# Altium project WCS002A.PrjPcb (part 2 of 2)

## Sheet WCS002A_HostInterface_ADC.SchDoc: Host Interface
size 558 x 431 mm; Date: Not shown in title block; ApprovedBy: Not shown in title block; CheckedBy: Not shown in title block; Author: Not shown in title block; CompanyName: Not shown in title block; Engineer: Not shown in title block; Organization: Not shown in title block; Address1: Not shown in title block; Address2: Not shown in title block; Address3: Not shown in title block; Address4: Not shown in title block; DocumentNumber: 3; Revision: Use project parameter SCH_Rev; SheetNumber: 3; SheetTotal: 6; PageSetup: Record=PageOptions¦CenterHorizontal=True¦CenterVertical=True¦PrintScale=1.00¦XCorrection=1.00¦YCorrection=1.00¦PrintKind=0¦BorderSize=5000000¦LeftOffset=0¦BottomOffset=0¦Orientation=2¦PaperLength=1000¦PaperWidth=1000¦Scale=100¦PaperSource=15¦PrintQuality=600¦MediaType=1¦DitherType=10¦PaperKind=Letter¦PrintScaleMode=1
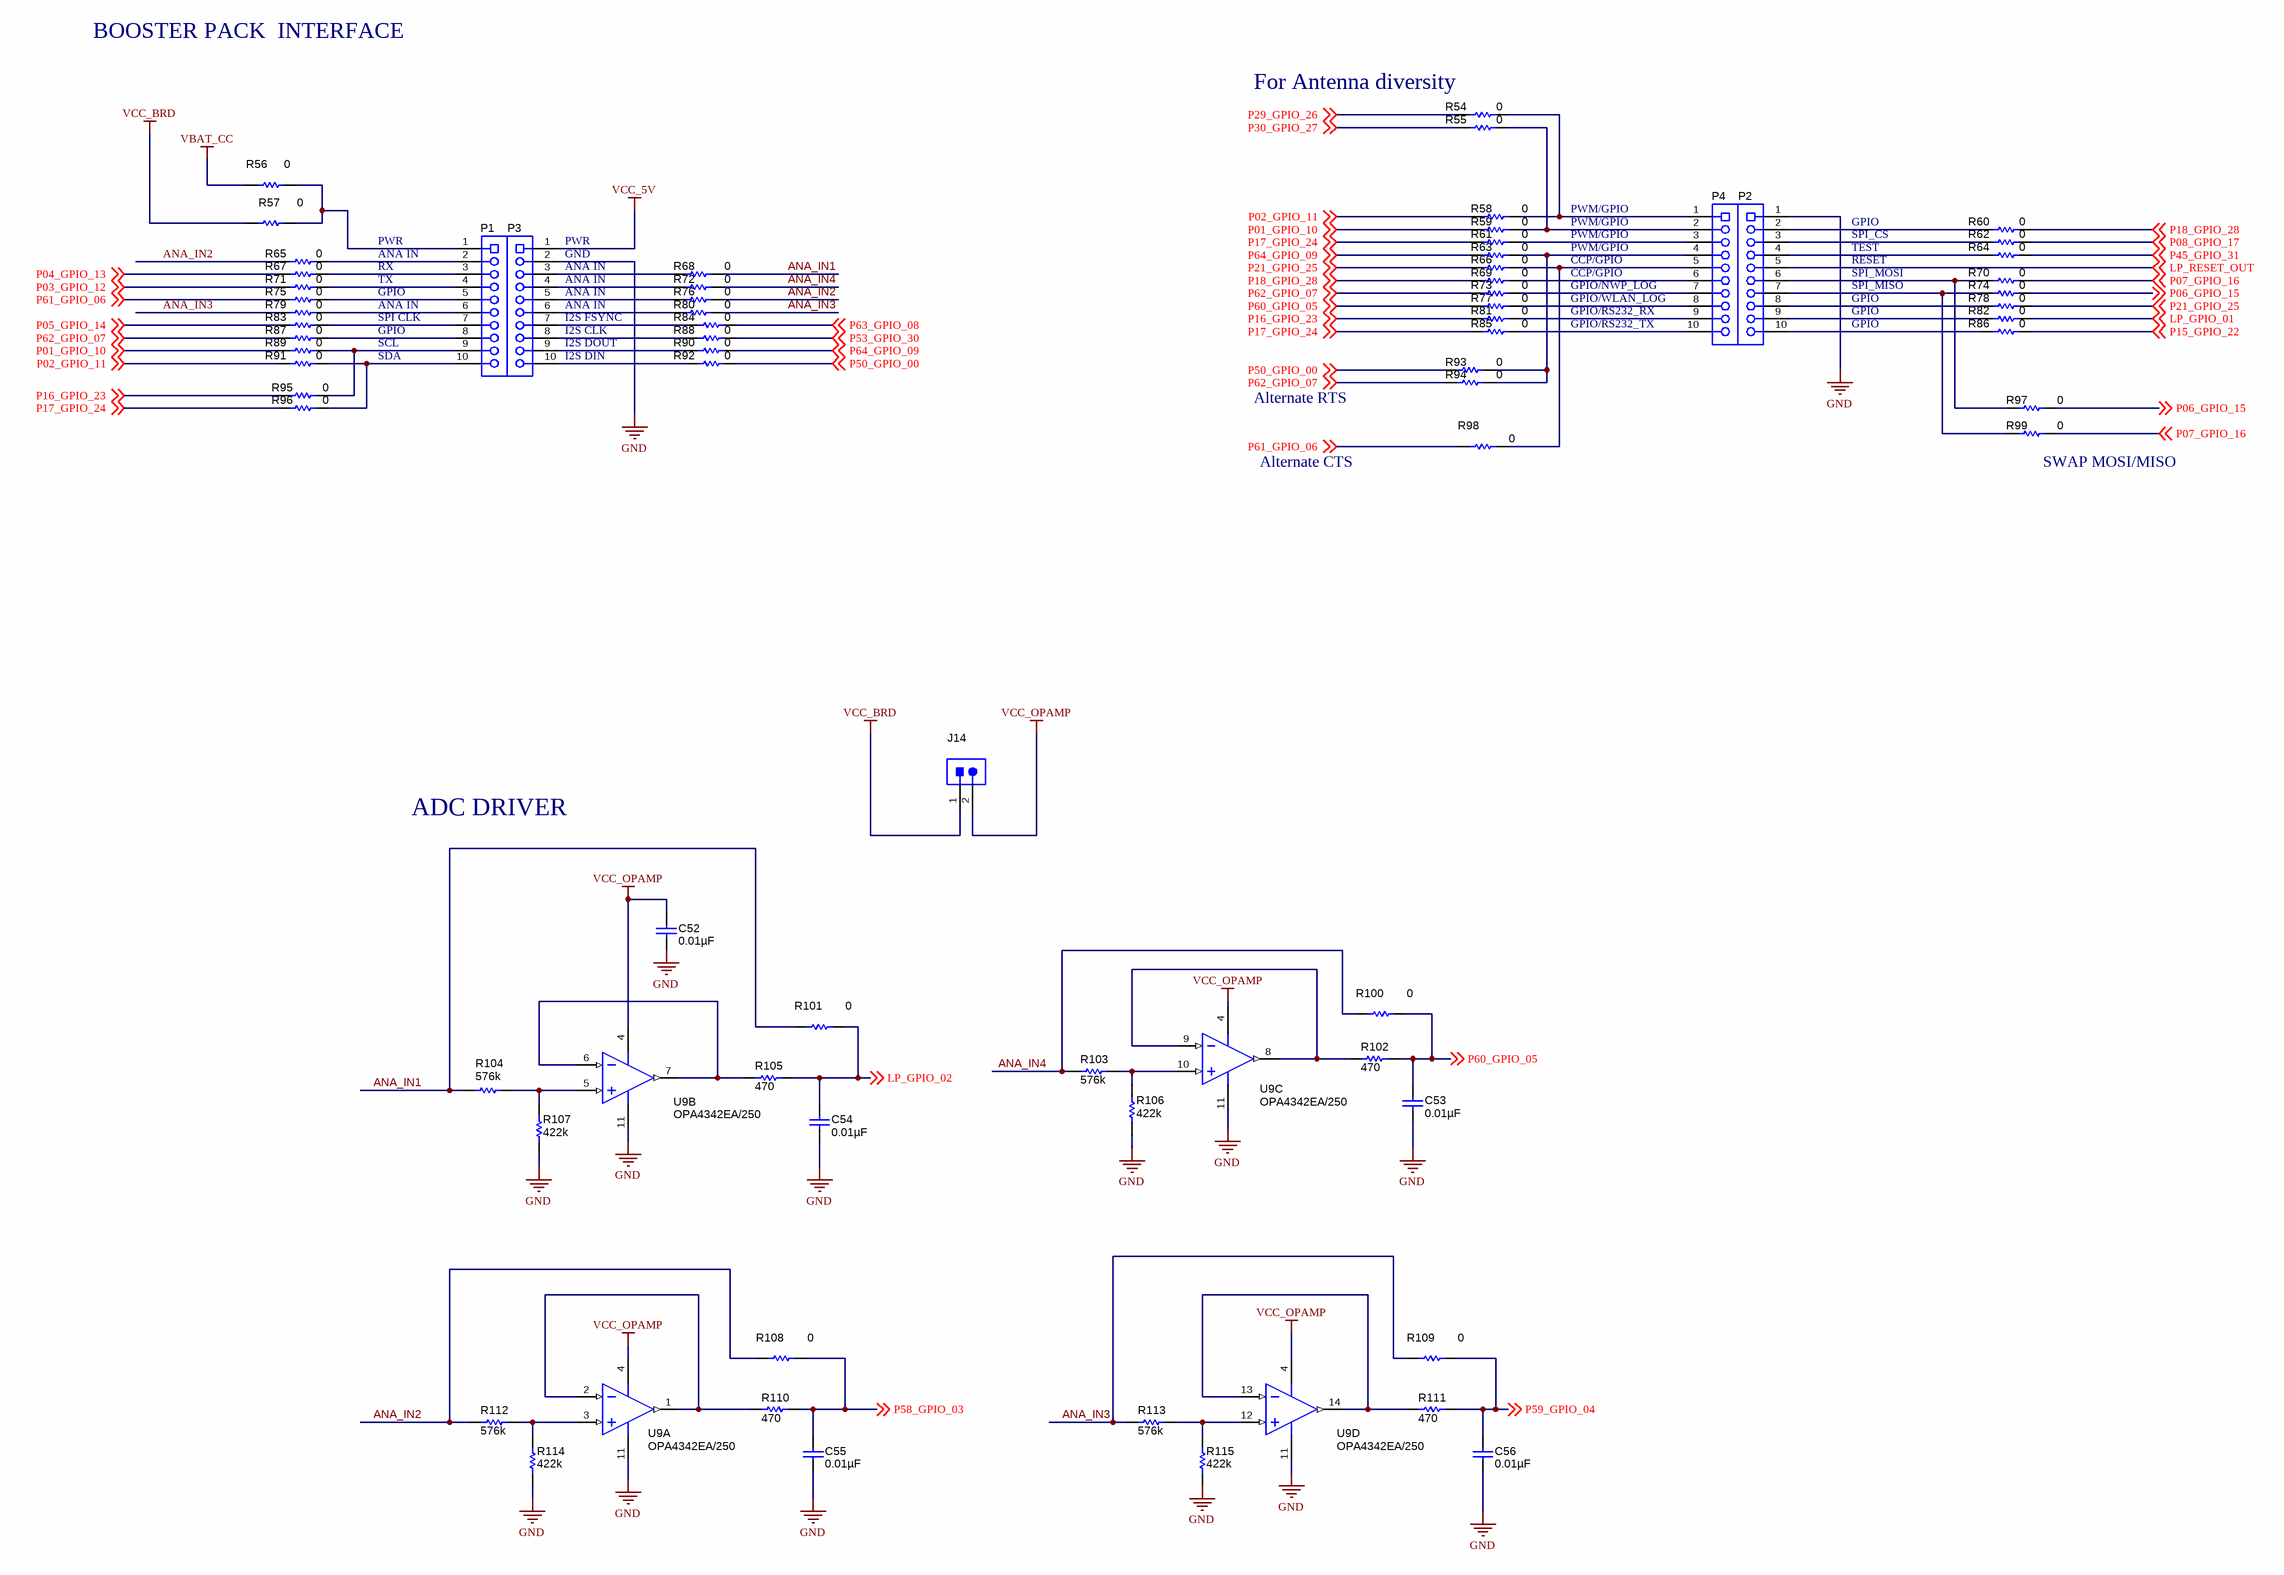
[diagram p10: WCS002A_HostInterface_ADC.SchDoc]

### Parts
C52  ValueDisplayed: 0.01µF  [0402]  (hidden comment: GRM155R61A103KA01D)
C53  ValueDisplayed: 0.01µF  [0402]  (hidden comment: C1005X7R1C103K)
C54  ValueDisplayed: 0.01µF  [0402]  (hidden comment: C1005X7R1C103K)
C55  ValueDisplayed: 0.01µF  [0402]  (hidden comment: C1005X7R1C103K)
C56  ValueDisplayed: 0.01µF  [0402]  (hidden comment: C1005X7R1C103K)
J14  61300211121  [WURTH_61300211121]  (value not drawn)
P1  SSW-110-23-F-S  [CONN_SSW-110-23-F-S]  (value not drawn)
P2  SSW-110-23-F-S  [CONN_SSW-110-23-F-S]  (value not drawn)
P3  SSW-110-23-F-S  [CONN_SSW-110-23-F-S]  (value not drawn)
P4  SSW-110-23-F-S  [CONN_SSW-110-23-F-S]  (value not drawn)
R54  ValueDisplayed: 0  [0402]  (hidden comment: ERJ-2GE0R00X)
R55  ValueDisplayed: 0  [0402]  (hidden comment: ERJ-2GE0R00X)
R56  ValueDisplayed: 0  [0603]  (hidden comment: ERJ-3GEY0R00V)
R57  ValueDisplayed: 0  [0603]  (hidden comment: ERJ-3GEY0R00V)
R58  ValueDisplayed: 0  [0402]  (hidden comment: ERJ-2GE0R00X)
R59  ValueDisplayed: 0  [0402]  (hidden comment: ERJ-2GE0R00X)
R60  ValueDisplayed: 0  [0402]  (hidden comment: ERJ-2GE0R00X)
R61  ValueDisplayed: 0  [0402]  (hidden comment: ERJ-2GE0R00X)
R62  ValueDisplayed: 0  [0402]  (hidden comment: ERJ-2GE0R00X)
R63  ValueDisplayed: 0  [0402]  (hidden comment: ERJ-2GE0R00X)
R64  ValueDisplayed: 0  [0402]  (hidden comment: ERJ-2GE0R00X)
R65  ValueDisplayed: 0  [0402]  (hidden comment: ERJ-2GE0R00X)
R66  ValueDisplayed: 0  [0402]  (hidden comment: ERJ-2GE0R00X)
R67  ValueDisplayed: 0  [0402]  (hidden comment: ERJ-2GE0R00X)
R68  ValueDisplayed: 0  [0402]  (hidden comment: ERJ-2GE0R00X)
R69  ValueDisplayed: 0  [0402]  (hidden comment: ERJ-2GE0R00X)
R70  ValueDisplayed: 0  [0402]  (hidden comment: ERJ-2GE0R00X)
R71  ValueDisplayed: 0  [0402]  (hidden comment: ERJ-2GE0R00X)
R72  ValueDisplayed: 0  [0402]  (hidden comment: ERJ-2GE0R00X)
R73  ValueDisplayed: 0  [0402]  (hidden comment: ERJ-2GE0R00X)
R74  ValueDisplayed: 0  [0402]  (hidden comment: ERJ-2GE0R00X)
R75  ValueDisplayed: 0  [0402]  (hidden comment: ERJ-2GE0R00X)
R76  ValueDisplayed: 0  [0402]  (hidden comment: ERJ-2GE0R00X)
R77  ValueDisplayed: 0  [0402]  (hidden comment: ERJ-2GE0R00X)
R78  ValueDisplayed: 0  [0402]  (hidden comment: ERJ-2GE0R00X)
R79  ValueDisplayed: 0  [0402]  (hidden comment: ERJ-2GE0R00X)
R80  ValueDisplayed: 0  [0402]  (hidden comment: ERJ-2GE0R00X)
R81  ValueDisplayed: 0  [0402]  (hidden comment: ERJ-2GE0R00X)
R82  ValueDisplayed: 0  [0402]  (hidden comment: ERJ-2GE0R00X)
R83  ValueDisplayed: 0  [0402]  (hidden comment: ERJ-2GE0R00X)
R84  ValueDisplayed: 0  [0402]  (hidden comment: ERJ-2GE0R00X)
R85  ValueDisplayed: 0  [0402]  (hidden comment: ERJ-2GE0R00X)
R86  ValueDisplayed: 0  [0402]  (hidden comment: ERJ-2GE0R00X)
R87  ValueDisplayed: 0  [0402]  (hidden comment: ERJ-2GE0R00X)
R88  ValueDisplayed: 0  [0402]  (hidden comment: ERJ-2GE0R00X)
R89  ValueDisplayed: 0  [0402]  (hidden comment: ERJ-2GE0R00X)
R90  ValueDisplayed: 0  [0402]  (hidden comment: ERJ-2GE0R00X)
R91  ValueDisplayed: 0  [0402]  (hidden comment: ERJ-2GE0R00X)
R92  ValueDisplayed: 0  [0402]  (hidden comment: ERJ-2GE0R00X)
R93  ValueDisplayed: 0  [0402]  (hidden comment: ERJ-2GE0R00X)
R94  ValueDisplayed: 0  [0402]  (hidden comment: ERJ-2GE0R00X)
R95  ValueDisplayed: 0  [0402]  (hidden comment: ERJ-2GE0R00X)
R96  ValueDisplayed: 0  [0402]  (hidden comment: ERJ-2GE0R00X)
R97  ValueDisplayed: 0  [0402]  (hidden comment: ERJ-2GE0R00X)
R98  ValueDisplayed: 0  [0402]  (hidden comment: ERJ-2GE0R00X)
R99  ValueDisplayed: 0  [0402]  (hidden comment: ERJ-2GE0R00X)
R100  ValueDisplayed: 0  [0402]  (hidden comment: ERJ-2GE0R00X)
R101  ValueDisplayed: 0  [0402]  (hidden comment: ERJ-2GE0R00X)
R102  ValueDisplayed: 470  [0402]  (hidden comment: ERJ-2RKF4700X)
R103  ValueDisplayed: 576k  [0402]  (hidden comment: CRCW0402576KFKED)
R104  ValueDisplayed: 576k  [0402]  (hidden comment: CRCW0402576KFKED)
R105  ValueDisplayed: 470  [0402]  (hidden comment: ERJ-2RKF4700X)
R106  ValueDisplayed: 422k  [0402]  (hidden comment: CRCW0402422KFKED)
R107  ValueDisplayed: 422k  [0402]  (hidden comment: CRCW0402422KFKED)
R108  ValueDisplayed: 0  [0402]  (hidden comment: ERJ-2GE0R00X)
R109  ValueDisplayed: 0  [0402]  (hidden comment: ERJ-2GE0R00X)
R110  ValueDisplayed: 470  [0402]  (hidden comment: ERJ-2RKF4700X)
R111  ValueDisplayed: 470  [0402]  (hidden comment: ERJ-2RKF4700X)
R112  ValueDisplayed: 576k  [0402]  (hidden comment: CRCW0402576KFKED)
R113  ValueDisplayed: 576k  [0402]  (hidden comment: CRCW0402576KFKED)
R114  ValueDisplayed: 422k  [0402]  (hidden comment: CRCW0402422KFKED)
R115  ValueDisplayed: 422k  [0402]  (hidden comment: CRCW0402422KFKED)
U9  OPA4342EA/250  [PW0014A_N]  (parts A,B,C,D of 4)

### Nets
GND: C52.2 C53.2 C54.2 C55.2 C56.2 P2.1 P3.2 R106.1 R107.1 R114.1 R115.1 U9.11(V-)
VBAT_CC: R56.1
VCC_5V: P3.1
VCC_BRD: J14.1 R57.1
VCC_OPAMP: C52.1 J14.2 U9.4(V+)
ANA_IN1: R68.2 R101.1 R104.1
ANA_IN2: R65.1 R76.2 R108.1 R112.1
ANA_IN3: R79.1 R80.2 R109.1 R113.1
ANA_IN4: R72.2 R100.1 R103.1
LP_GPIO_01: R82.2 ; off-sheet LP_GPIO_01
LP_GPIO_02: C54.1 R101.2 R105.2 ; off-sheet LP_GPIO_02
LP_RESET_OUT: P2.5 ; off-sheet LP_RESET_OUT
P01_GPIO_10: R59.1 R89.1 ; off-sheet P01_GPIO_10
P02_GPIO_11: R58.1 R91.1 ; off-sheet P02_GPIO_11
P03_GPIO_12: R71.1 ; off-sheet P03_GPIO_12
P04_GPIO_13: R67.1 ; off-sheet P04_GPIO_13
P05_GPIO_14: R83.1 ; off-sheet P05_GPIO_14
P06_GPIO_15: R74.2 R97.2 ; off-sheet P06_GPIO_15
P07_GPIO_16: R70.2 R99.2 ; off-sheet P07_GPIO_16
P08_GPIO_17: R62.2 ; off-sheet P08_GPIO_17
P15_GPIO_22: R86.2 ; off-sheet P15_GPIO_22
P16_GPIO_23: R81.1 R95.1 ; off-sheet P16_GPIO_23
P17_GPIO_24: R61.1 R85.1 R96.1 ; off-sheet P17_GPIO_24
P18_GPIO_28: R60.2 R69.1 ; off-sheet P18_GPIO_28
P21_GPIO_25: R66.1 R78.2 ; off-sheet P21_GPIO_25
P29_GPIO_26: R54.1 ; off-sheet P29_GPIO_26
P30_GPIO_27: R55.1 ; off-sheet P30_GPIO_27
P45_GPIO_31: R64.2 ; off-sheet P45_GPIO_31
P50_GPIO_00: R92.2 R93.1 ; off-sheet P50_GPIO_00
P53_GPIO_30: R88.2 ; off-sheet P53_GPIO_30
P58_GPIO_03: C55.1 R108.2 R110.2 ; off-sheet P58_GPIO_03
P59_GPIO_04: C56.1 R109.2 R111.2 ; off-sheet P59_GPIO_04
P60_GPIO_05: C53.1 R77.1 R100.2 R102.2 ; off-sheet P60_GPIO_05
P61_GPIO_06: R75.1 R98.1 ; off-sheet P61_GPIO_06
P62_GPIO_07: R73.1 R87.1 R94.1 ; off-sheet P62_GPIO_07
P63_GPIO_08: R84.2 ; off-sheet P63_GPIO_08
P64_GPIO_09: R63.1 R90.2 ; off-sheet P64_GPIO_09
NetP1_1: P1.1 R56.2 R57.2
NetP1_2: P1.2 R65.2
NetP1_3: P1.3 R67.2
NetP1_4: P1.4 R71.2
NetP1_5: P1.5 R75.2
NetP1_6: P1.6 R79.2
NetP1_7: P1.7 R83.2
NetP1_8: P1.8 R87.2
NetP1_9: P1.9 R89.2 R95.2
NetP1_10: P1.10 R91.2 R96.2
NetP2_2: P2.2 R60.1
NetP2_3: P2.3 R62.1
NetP2_4: P2.4 R64.1
NetP2_6: P2.6 R70.1 R97.1
NetP2_7: P2.7 R74.1 R99.1
NetP2_8: P2.8 R78.1
NetP2_9: P2.9 R82.1
NetP2_10: P2.10 R86.1
NetP3_3: P3.3 R68.1
NetP3_4: P3.4 R72.1
NetP3_5: P3.5 R76.1
NetP3_6: P3.6 R80.1
NetP3_7: P3.7 R84.1
NetP3_8: P3.8 R88.1
NetP3_9: P3.9 R90.1
NetP3_10: P3.10 R92.1
NetP4_1: P4.1 R54.2 R58.2
NetP4_2: P4.2 R55.2 R59.2
NetP4_3: P4.3 R61.2
NetP4_4: P4.4 R63.2 R93.2 R94.2
NetP4_5: P4.5 R66.2 R98.2
NetP4_6: P4.6 R69.2
NetP4_7: P4.7 R73.2
NetP4_8: P4.8 R77.2
NetP4_9: P4.9 R81.2
NetP4_10: P4.10 R85.2
NetR102_1: R102.1 U9.8(OUT_C) U9.9(IN_C-)
NetR103_2: R103.2 R106.2 U9.10(IN_C+)
NetR104_2: R104.2 R107.2 U9.5(IN_B+)
NetR105_1: R105.1 U9.6(IN_B-) U9.7(OUT_B)
NetR110_1: R110.1 U9.1(OUT_A) U9.2(IN_A-)
NetR111_1: R111.1 U9.13(IN_D-) U9.14(OUT_D)
NetR112_2: R112.2 R114.2 U9.3(IN_A+)
NetR113_2: R113.2 R115.2 U9.12(IN_D+)

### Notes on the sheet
- BOOSTER PACK  INTERFACE
- For Antenna diversity
- PWR
- ANA IN
- (near P3) PWR
- (near P3) GND
- PWM/GPIO
- GPIO
- SPI_CS
- TEST
- RX
- TX
- SPI CLK
- (near P3) I2S FSYNC
- (near P3) ANA IN
- CCP/GPIO
- GPIO/NWP_LOG
- GPIO/WLAN_LOG
- GPIO/RS232_RX
- GPIO/RS232_TX
- RESET
- SPI_MOSI
- SPI_MISO
- SCL
- SDA
- (near P3) I2S CLK
- (near P3) I2S DOUT
- (near P3) I2S DIN
- Alternate RTS
- Alternate CTS
- (near R99) SWAP MOSI/MISO
- ADC DRIVER

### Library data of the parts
C52 = GRM155R61A103KA01D: CAP, CERM, 0.01 µF, 10 V, +/- 10%, X5R, 0402; Manufacturer: MuRata; Polarized: N; CompType: Capacitor; Value: 0.01uF; U/M: EA; Cap_F: 0.00000001; Tolerance_%: 10; Value1: Unknown; Value2: 10V; TaMin_C: -55; TaMax_C: 85
C53-C56 = C1005X7R1C103K: CAP, CERM, 0.01 µF, 16 V, +/- 10%, X7R, 0402; Manufacturer: TDK; Polarized: N; CompType: Capacitor; Value: 0.01uF; U/M: EA; Cap_F: 0.00000001; Tolerance_%: 10; ESR_ohm: 0.0623; Value1: 0.0623 ohm; VDC_V: 16; Value2: 16V; TaMin_C: -55; TaMax_C: 125
J14 = 61300211121: Header, 2.54 mm, 2x1, Gold, TH; Manufacturer: Wurth Elektronik; SymbolCreator: a0412235
P1-P4 = SSW-110-23-F-S: Connector, Receptacle, 100mil, 10x1, Gold plated, TH; Manufacturer: Samtec; SymbolCreator: a0411947; U/M: EA
R54 R55 R58-R99 = ERJ-2GE0R00X: RES, 0, 5%, 0.063 W, 0402; Manufacturer: Panasonic; CompType: Resistor; Value: 0; Value_Code: 0000; Tolerance_%: 5; Power_W: 0.063; Value2: 0.063W; VDC_V: 50; TempCo: 600 ppm/C; EIA_Code: E24; U/M: EA
R56 R57 = ERJ-3GEY0R00V: RES, 0, 5%, 0.1 W, 0603; Manufacturer: Panasonic; CompType: Resistor; Value: 0; Value_Code: 0000; Tolerance_%: 5; Power_W: 0.1; Value2: 0.1W; VDC_V: 50; TempCo: 600 ppm/C; EIA_Code: E24; U/M: EA; AEC Category: Q200
R100 R101 R108 R109 = ERJ-2GE0R00X: RES, 0, 5%, 0.063 W, 0402; Manufacturer: Panasonic; CompType: Resistor; Value: 0; Value_Code: 0000; Tolerance_%: 5; Power_W: 0.063; Value2: 0.063W; VDC_V: 50; TempCo: 600 ppm/C; EIA_Code: E24; U/M: EA; AEC Category: Q200
R102 R105 R110 R111 = ERJ-2RKF4700X: RES, 470, 1%, 0.1 W, 0402; Manufacturer: Panasonic; CompType: Resistor; Value: 470; Value_Code: 470R; Tolerance_%: 1; Power_W: 0.1; Value2: 0.1W; VDC_V: 50; TempCo: 100 ppm/C; U/M: EA
R103 R104 R112 R113 = CRCW0402576KFKED: RES, 576 k, 1%, 0.063 W, 0402; Manufacturer: Vishay-Dale; CompType: Resistor; Value: 576k; Res_ohm: 576000; Tolerance_%: 1; Power_W: 0.063; Value2: 0.063W; VDC_V: 50; TempCo: 100 ppm/C; EIA_Code: E96; U/M: EA
R106 R107 R114 R115 = CRCW0402422KFKED: RES, 422 k, 1%, 0.063 W, 0402; Manufacturer: Vishay-Dale; CompType: Resistor; Value: 422k; Res_ohm: 422000; Tolerance_%: 1; Power_W: 0.063; Value2: 0.063W; VDC_V: 50; TempCo: 100 ppm/C; EIA_Code: E96; U/M: EA
U9 = OPA4342EA/250: Low Cost, Low Power, Rail-to-Rail Operational Amplifier MicroAmplifier(TM) Series, 2.7 to 5.5 V, -55 to 125 degC, 14-pin SOP (PW0014A), Green (RoHS & no Sb/Br); Manufacturer: Texas Instruments; Alternate Manufacturer: None; Alternate PartNumber: Equivalent; CMRR(Min)(dB): 76; GBW(Typ)(MHz): 1; IIB(Max)(pA): 10; Iq per channel(Max)(mA): 0.25; Number of Channels: 4; Offset Drift(Typ)(uV/C): 3; Packing: SMALL T&R; Rating: Catalog; Sub Family: Low Input Bias Current Amp (<=10pA), Low Power Amp (<=500uA), Low Supply Voltage Amplifier (<=2.7V), Precision Amplifier; Total Supply Voltage(Max)(+5V is 5, +/-5V is 10): 5.5; Total Supply Voltage(Min)(+5V is 5, +/-5V is 10): 2.7; Vio (25C)(Max)(mV): 6

## Sheet WCS002A_PowerLedsSwitchSensors.SchDoc: Power LEDs Switch Sensor
size 558 x 431 mm; Date: Not shown in title block; ApprovedBy: Not shown in title block; CheckedBy: Not shown in title block; Author: Not shown in title block; CompanyName: Not shown in title block; Engineer: Not shown in title block; Organization: Not shown in title block; Address1: Not shown in title block; Address2: Not shown in title block; Address3: Not shown in title block; Address4: Not shown in title block; DocumentNumber: 5; Revision: Use project parameter SCH_Rev; SheetNumber: 5; SheetTotal: 6; PageSetup: Record=PageOptions¦CenterHorizontal=True¦CenterVertical=True¦PrintScale=1.00¦XCorrection=1.00¦YCorrection=1.00¦PrintKind=0¦BorderSize=5000000¦LeftOffset=0¦BottomOffset=0¦Orientation=2¦PaperLength=1000¦PaperWidth=1000¦Scale=100¦PaperSource=15¦PrintQuality=600¦MediaType=1¦DitherType=10¦PaperKind=Letter¦PrintScaleMode=1
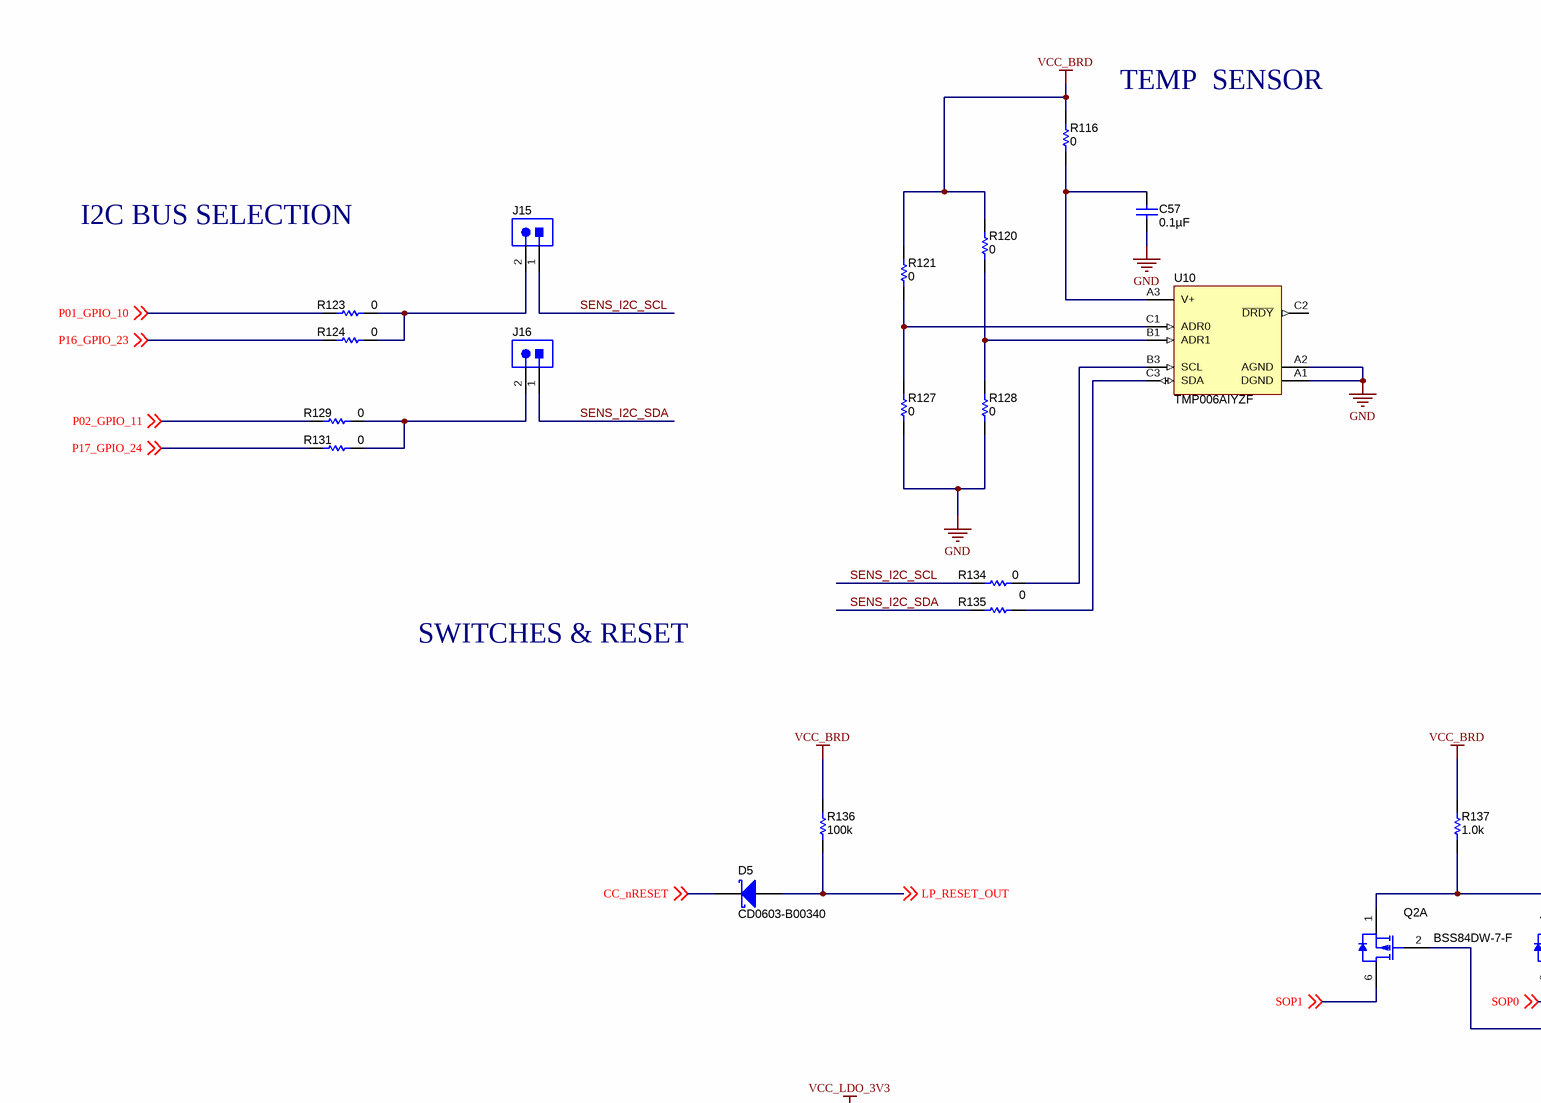
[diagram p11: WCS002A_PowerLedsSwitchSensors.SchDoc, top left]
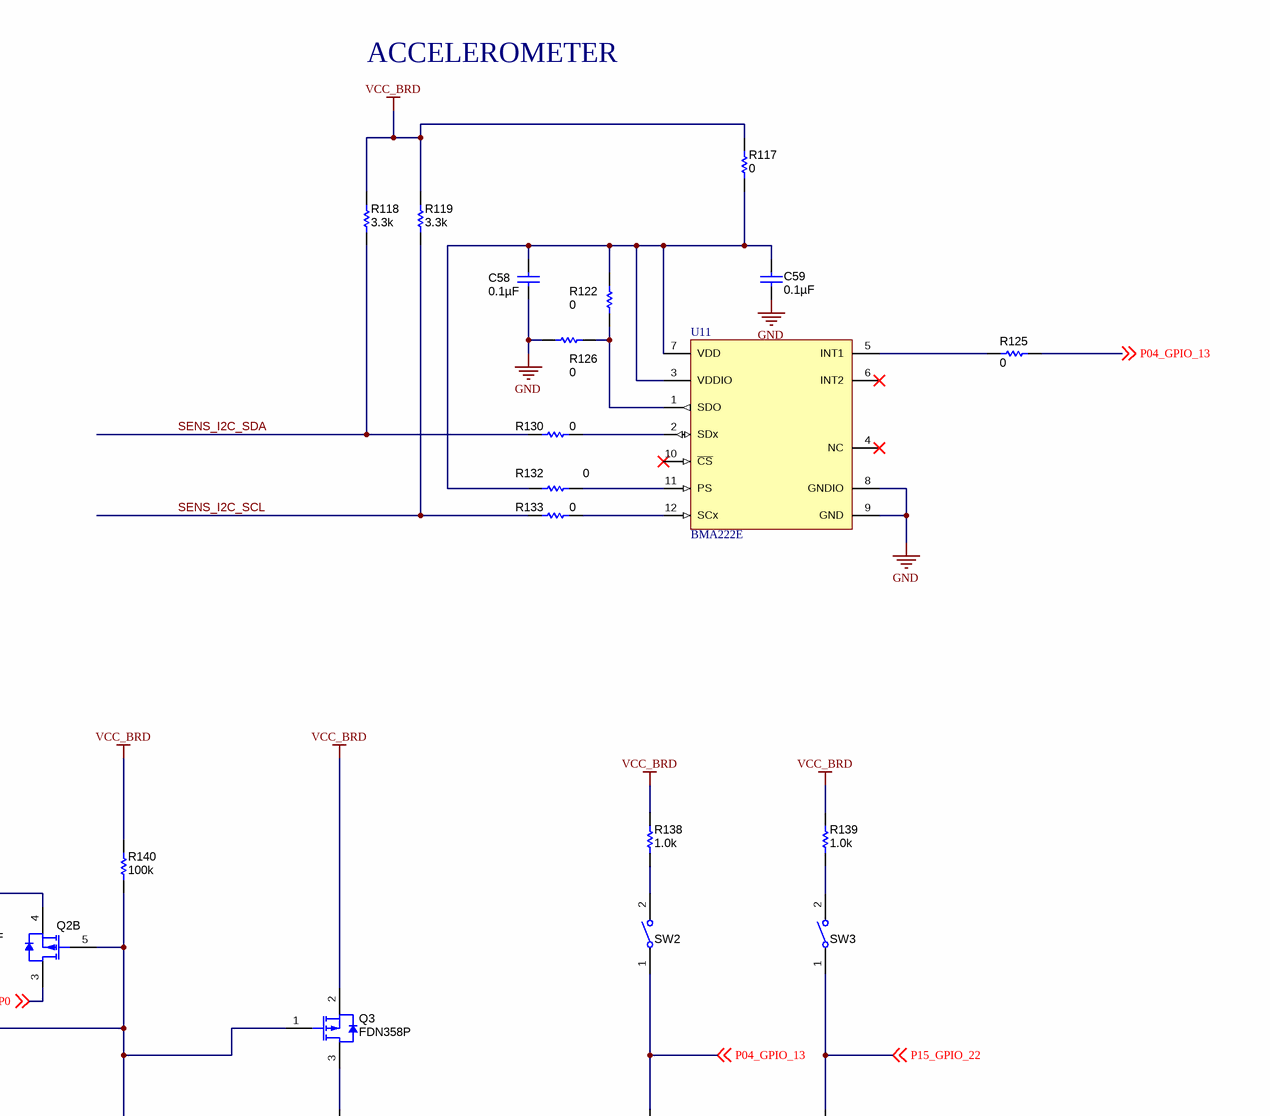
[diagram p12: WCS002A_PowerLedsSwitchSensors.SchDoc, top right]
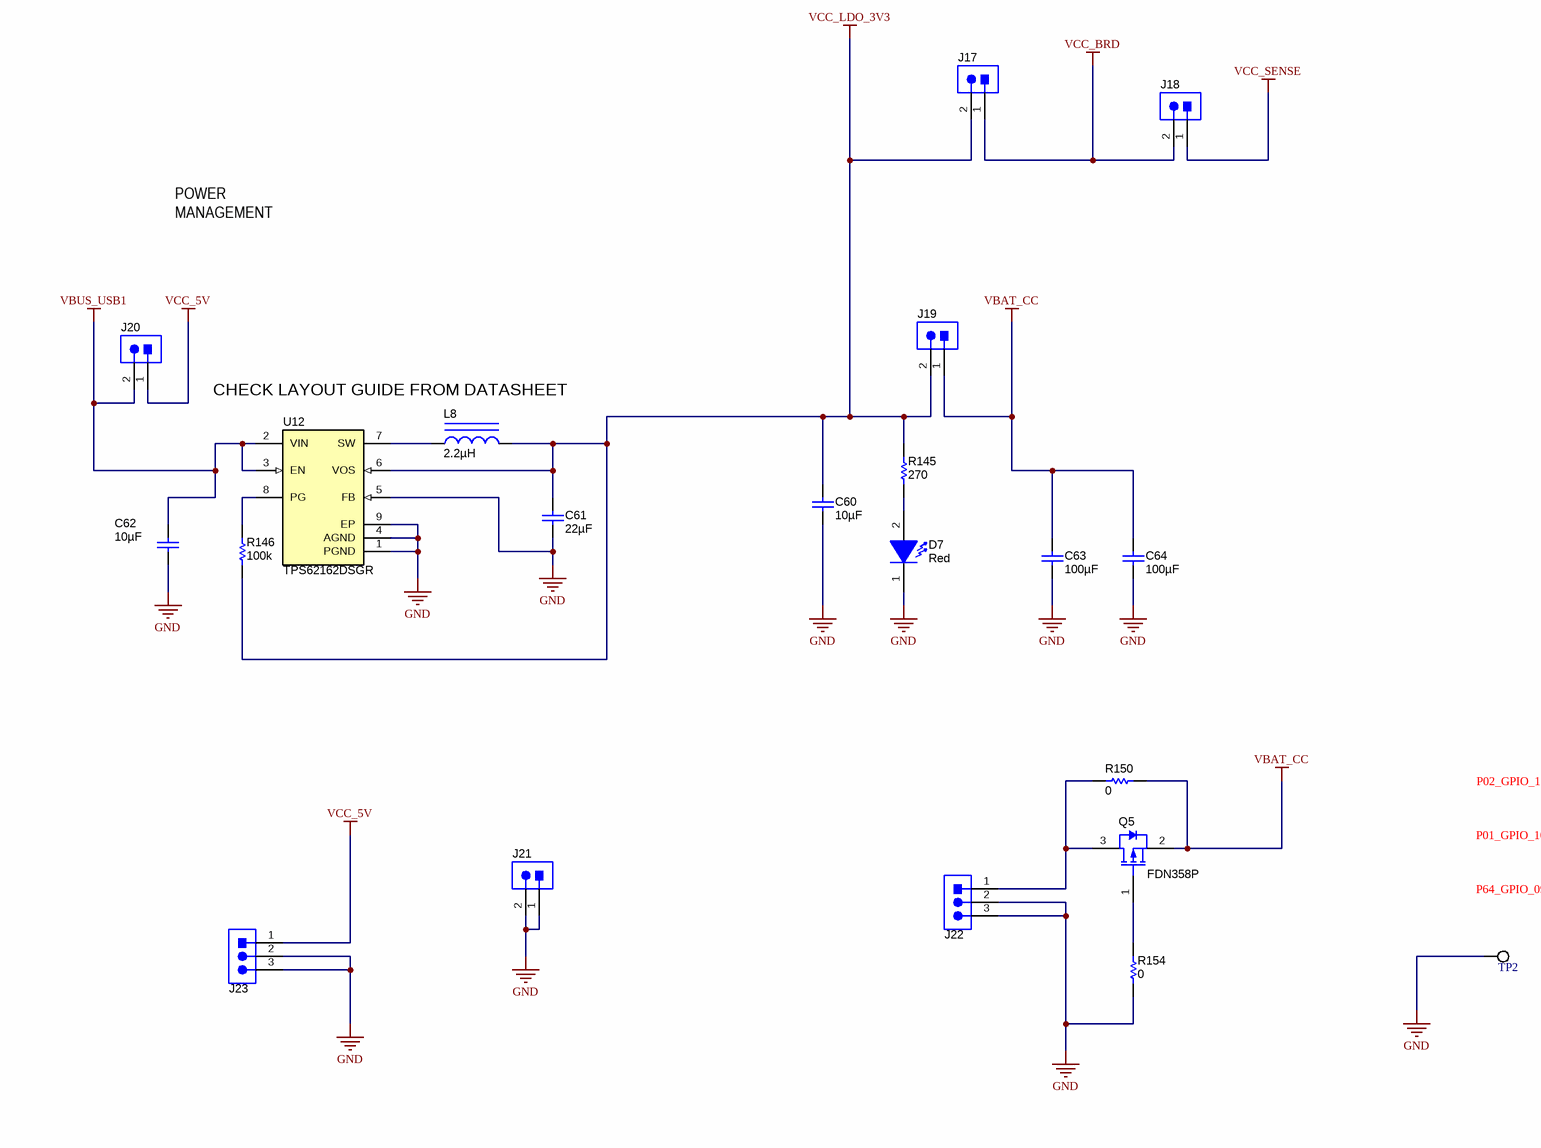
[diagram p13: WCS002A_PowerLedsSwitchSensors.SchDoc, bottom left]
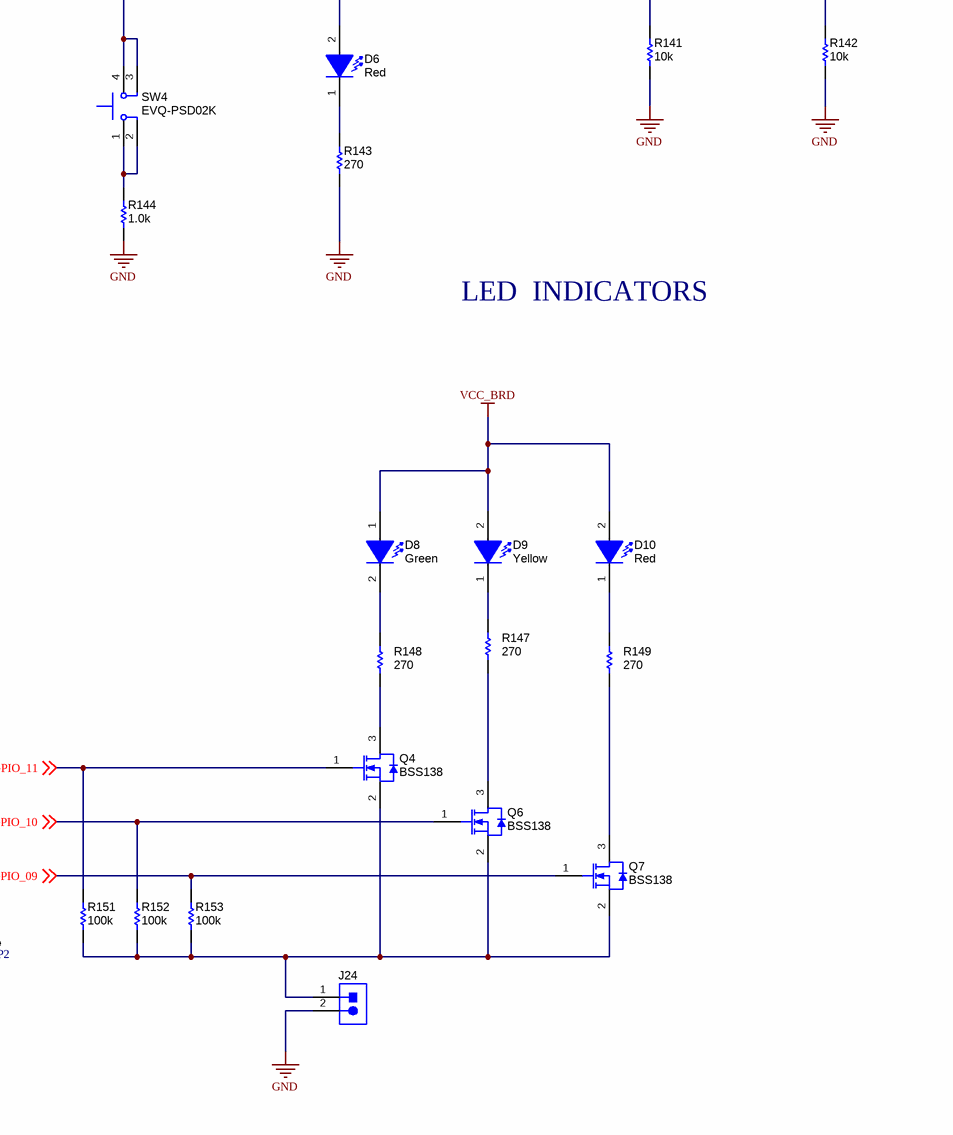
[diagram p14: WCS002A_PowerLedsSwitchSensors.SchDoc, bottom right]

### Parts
C57  ValueDisplayed: 0.1µF  [0402]  (hidden comment: C1005X5R1A104K050BA)
C58  ValueDisplayed: 0.1µF  [0402]  (hidden comment: C1005X5R1A104K050BA)
C59  ValueDisplayed: 0.1µF  [0402]  (hidden comment: C1005X5R1A104K050BA)
C60  ValueDisplayed: 10µF  [0805]  (hidden comment: GRM21BR61A106KE19L)
C61  ValueDisplayed: 22µF  [0805_HV]  (hidden comment: C2012X5R1C226K125AC)
C62  ValueDisplayed: 10µF  [0805]  (hidden comment: GRM21BR61A106KE19L)
C63  ValueDisplayed: 100µF  [1206]  (hidden comment: GRM31CR60J107ME39L)
C64  ValueDisplayed: 100µF  [1206]  (hidden comment: GRM31CR60J107ME39L)
D5  CD0603-B00340  [Diode_0603]
D6  value Red  [SML-31_Red]  (hidden comment: SML-311UTT86)
D7  value Red  [SML-31_Red]  (hidden comment: SML-311UTT86)
D8  value Green  [LED_SML-LX0603GW]  (hidden comment: SML-LX0603GW-TR)
D9  value Yellow  [WL-SMCW_YELLOW]  (hidden comment: 150060YS75000)
D10  value Red  [SML-31_Red]  (hidden comment: SML-311UTT86)
J15  61300211121  [WURTH_61300211121]  (value not drawn)
J16  61300211121  [WURTH_61300211121]  (value not drawn)
J17  61300211121  [WURTH_61300211121]  (value not drawn)
J18  61300211121  [WURTH_61300211121]  (value not drawn)
J19  61300211121  [WURTH_61300211121]  (value not drawn)
J20  61300211121  [WURTH_61300211121]  (value not drawn)
J21  61300211121  [WURTH_61300211121]  (value not drawn)
J22  61300311121  [WURTH_61300311121]  (value not drawn)
J23  61300311121  [WURTH_61300311121]  (value not drawn)
J24  61300211121  [WURTH_61300211121]  (value not drawn)
L8  ValueDisplayed: 2.2µH  [0805_140]  (hidden comment: BRC2012T2R2MD)
Q2  BSS84DW-7-F  [SOT-363]  (parts A,B of 2)
Q3  FDN358P  [SSOT-3]
Q4  BSS138  [SOT-23]
Q5  FDN358P  [SSOT-3]
Q6  BSS138  [SOT-23]
Q7  BSS138  [SOT-23]
R116  ValueDisplayed: 0  [0402]  (hidden comment: ERJ-2GE0R00X)
R117  ValueDisplayed: 0  [0402]  (hidden comment: ERJ-2GE0R00X)
R118  ValueDisplayed: 3.3k  [0402]  (hidden comment: CRCW04023K30JNED)
R119  ValueDisplayed: 3.3k  [0402]  (hidden comment: CRCW04023K30JNED)
R120  ValueDisplayed: 0  [0402]  (hidden comment: ERJ-2GE0R00X)
R121  ValueDisplayed: 0  [0402]  (hidden comment: ERJ-2GE0R00X)
R122  ValueDisplayed: 0  [0402]  (hidden comment: ERJ-2GE0R00X)
R123  ValueDisplayed: 0  [0402]  (hidden comment: ERJ-2GE0R00X)
R124  ValueDisplayed: 0  [0402]  (hidden comment: ERJ-2GE0R00X)
R125  ValueDisplayed: 0  [0805_HV]  (hidden comment: ERJ-6GEY0R00V)
R126  ValueDisplayed: 0  [0402]  (hidden comment: ERJ-2GE0R00X)
R127  ValueDisplayed: 0  [0402]  (hidden comment: ERJ-2GE0R00X)
R128  ValueDisplayed: 0  [0402]  (hidden comment: ERJ-2GE0R00X)
R129  ValueDisplayed: 0  [0402]  (hidden comment: ERJ-2GE0R00X)
R130  ValueDisplayed: 0  [0402]  (hidden comment: ERJ-2GE0R00X)
R131  ValueDisplayed: 0  [0402]  (hidden comment: ERJ-2GE0R00X)
R132  ValueDisplayed: 0  [0402]  (hidden comment: ERJ-2GE0R00X)
R133  ValueDisplayed: 0  [0402]  (hidden comment: ERJ-2GE0R00X)
R134  ValueDisplayed: 0  [0402]  (hidden comment: ERJ-2GE0R00X)
R135  ValueDisplayed: 0  [0402]  (hidden comment: ERJ-2GE0R00X)
R136  ValueDisplayed: 100k  [0402]  (hidden comment: CRCW0402100KJNED)
R137  ValueDisplayed: 1.0k  [0402]  (hidden comment: CRCW04021K00JNED)
R138  ValueDisplayed: 1.0k  [0402]  (hidden comment: CRCW04021K00JNED)
R139  ValueDisplayed: 1.0k  [0402]  (hidden comment: CRCW04021K00JNED)
R140  ValueDisplayed: 100k  [0402]  (hidden comment: ERJ-2RKF1003X)
R141  ValueDisplayed: 10k  [0402]  (hidden comment: CRCW040210K0JNED)
R142  ValueDisplayed: 10k  [0402]  (hidden comment: CRCW040210K0JNED)
R143  ValueDisplayed: 270  [0603]  (hidden comment: CRCW0603270RJNEA)
R144  ValueDisplayed: 1.0k  [0402]  (hidden comment: CRCW04021K00JNED)
R145  ValueDisplayed: 270  [0603]  (hidden comment: CRCW0603270RJNEA)
R146  ValueDisplayed: 100k  [0402]  (hidden comment: CRCW0402100KJNED)
R147  ValueDisplayed: 270  [0603]  (hidden comment: CRCW0603270RJNEA)
R148  ValueDisplayed: 270  [0603]  (hidden comment: CRCW0603270RJNEA)
R149  ValueDisplayed: 270  [0603]  (hidden comment: CRCW0603270RJNEA)
R150  ValueDisplayed: 0  [0603]  (hidden comment: ERJ-3GEY0R00V)
R151  ValueDisplayed: 100k  [0402]  (hidden comment: CRCW0402100KJNED)
R152  ValueDisplayed: 100k  [0402]  (hidden comment: CRCW0402100KJNED)
R153  ValueDisplayed: 100k  [0402]  (hidden comment: CRCW0402100KJNED)
R154  ValueDisplayed: 0  [0402]  (hidden comment: ERJ-2GE0R00X)
SW2  MJTP1117  [SW_MJTP1117]  (value not drawn)
SW3  MJTP1117  [SW_MJTP1117]  (value not drawn)
SW4  EVQ-PSD02K  [SW_EVQ-PSD02K]
TP2  5015  [Testpoint_Keystone_Miniature]  (value not drawn)
U10  TMP006AIYZF  [YZF0008AEAE]
U11  BMA222E  [12LGA]
U12  TPS62162DSGR  [DSG0008A]

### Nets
GND: C57.2 C58.2 C59.2 C60.2 C61.2 C62.2 C63.2 C64.2 D7.1(K) J21.1 J21.2 J22.2 J22.3 J23.2 J23.3 J24.2 R126.1 R127.1 R128.1 R141.2 R142.2 R143.1 R144.1 R154.1 TP2.1 U10.A1(DGND) U10.A2(AGND) U11.8(GNDIO) U11.9(GND) U12.1(PGND) U12.4(AGND) U12.5(FB) U12.9(EP)
VBAT_CC: C63.1 C64.1 J19.1 Q5.2(S) R150.2
VBUS_USB1: C62.1 J20.2 U12.2(VIN) U12.3(EN)
VCC_5V: J20.1 J23.1
VCC_BRD: D8.1(A) D9.2(A) D10.2(A) J17.1 J18.2 Q3.2(S) R116.2 R117.2 R118.1 R119.1 R120.2 R121.2 R136.1 R137.2 R138.1 R139.1 R140.2
VCC_LDO_3V3: C60.1 C61.1 J17.2 J19.2 L8.2 R145.1 R146.2 U12.6(VOS)
VCC_SENSE: J18.1
CC_nRESET: D5.1(K) ; off-sheet CC_nRESET
LP_RESET_OUT: D5.2(A) R136.2 ; off-sheet LP_RESET_OUT
P01_GPIO_10: Q6.1(G) R123.1 R152.1 ; off-sheet P01_GPIO_10
P02_GPIO_11: Q4.1(G) R129.1 R151.1 ; off-sheet P02_GPIO_11
P04_GPIO_13: R125.2 R141.1 SW2.1 ; off-sheet P04_GPIO_13
P15_GPIO_22: R142.1 SW3.1 ; off-sheet P15_GPIO_22
P16_GPIO_23: R124.1 ; off-sheet P16_GPIO_23
P17_GPIO_24: R131.1 ; off-sheet P17_GPIO_24
P64_GPIO_09: Q7.1(G) R153.1 ; off-sheet P64_GPIO_09
SENS_I2C_SCL: J15.1 R119.2 R133.1 R134.1
SENS_I2C_SDA: J16.1 R118.2 R130.1 R135.1
SOP0: Q2.3(D) ; off-sheet SOP0
SOP1: Q2.6(D) ; off-sheet SOP1
NetC57_1: C57.1 R116.1 U10.A3(V+)
NetC58_1: C58.1 C59.1 R117.1 R122.2 R132.2 U11.3(VDDIO) U11.7(VDD)
NetD6_1: D6.1(K) R143.2
NetD6_2: D6.2(A) Q3.3(D)
NetD7_2: D7.2(A) R145.2
NetD8_2: D8.2(K) R148.2
NetD9_1: D9.1(K) R147.2
NetD10_1: D10.1(K) R149.2
NetJ15_2: J15.2 R123.2 R124.2
NetJ16_2: J16.2 R129.2 R131.2
NetJ22_1: J22.1 Q5.3(D) R150.1
NetJ24_1: J24.1 Q4.2(S) Q6.2(S) Q7.2(S) R151.2 R152.2 R153.2
NetL8_1: L8.1 U12.7(SW)
NetQ2_1: Q2.1(S) Q2.4(S) R137.1
NetQ2_2: Q2.2(G) Q2.5(G) Q3.1(G) R140.1 SW4.3 SW4.4
NetQ4_3: Q4.3(D) R148.1
NetQ5_1: Q5.1(G) R154.2
NetQ6_3: Q6.3(D) R147.1
NetQ7_3: Q7.3(D) R149.1
NetR120_1: R120.1 R128.2 U10.B1(ADR1)
NetR121_1: R121.1 R127.2 U10.C1(ADR0)
NetR122_1: R122.1 R126.2 U11.1(SDO)
NetR125_1: R125.1 U11.5(INT1)
NetR130_2: R130.2 U11.2(SDx)
NetR132_1: R132.1 U11.11(PS)
NetR133_2: R133.2 U11.12(SCx)
NetR134_2: R134.2 U10.B3(SCL)
NetR135_2: R135.2 U10.C3(SDA)
NetR138_2: R138.2 SW2.2
NetR139_2: R139.2 SW3.2
NetR144_2: R144.2 SW4.1 SW4.2
NetR146_1: R146.1 U12.8(PG)

Not connected (* = marked no-connect by the designer): U10 C2(~{DRDY}); U11 4(NC)* 6(INT2)* 10(~{CS})*

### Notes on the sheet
- TEMP  SENSOR
- ACCELEROMETER
- I2C BUS SELECTION
- SWITCHES & RESET
- POWER
  MANAGEMENT
- LED  INDICATORS
- CHECK LAYOUT GUIDE FROM DATASHEET

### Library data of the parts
C57-C59 = C1005X5R1A104K050BA: CAP, CERM, 0.1 µF, 10 V, +/- 10%, X5R, 0402; Manufacturer: TDK; Polarized: N; CompType: Capacitor; Value: 0.1uF; U/M: EA; Cap_F: 0.0000001; Tolerance_%: 10; Value1: Unknown; Value2: 10V; TaMin_C: -55; TaMax_C: 85
C60 C62 = GRM21BR61A106KE19L: CAP, CERM, 10 µF, 10 V, +/- 10%, X5R, 0805; Manufacturer: MuRata; Polarized: N; CompType: Capacitor; Value: 10uF; U/M: EA; Cap_F: 0.00001; Tolerance_%: 10; ESR_ohm: 0.002; Value1: 0.002 ohm; Value2: 10V; TaMin_C: -55; TaMax_C: 85
C61 = C2012X5R1C226K125AC: CAP, CERM, 22 µF, 16 V, +/- 10%, X5R, 0805; Manufacturer: TDK; Polarized: N; CompType: Capacitor; Value: 22uF; U/M: EA; Cap_F: 0.000022; Tolerance_%: 10; Value1: Unknown; VDC_V: 16; Value2: 16V; TaMin_C: -55; TaMax_C: 85; Cap_Case: 0805; AEC Category: Q200
C63 C64 = GRM31CR60J107ME39L: CAP, CERM, 100 µF, 6.3 V, +/- 20%, X5R, 1206; Manufacturer: MuRata; Polarized: N; CompType: Capacitor; Value: 100uF; U/M: EA; Cap_F: 0.0001; Tolerance_%: 20; ESR_ohm: 0.003; Value1: 0.003 ohm; VDC_V: 6.3; Value2: 6.3V; TaMin_C: -55; TaMax_C: 85
D5 = CD0603-B00340: Diode, Schottky, 45 V, 0.03 A, 0603 Diode; Manufacturer: Bourns; U/M: EA; Vf_V: 0.37; Value: 45V; Value1: 0.03A; Value2: 0.37V; Io_A: 0.03; Vr_V: 45; TJmax_C: 125
D6 D7 D10 = SML-311UTT86: LED, Red, SMD; Manufacturer: Rohm; Type: AlInGaP; Vf_V: 1.8; Value2: 1.8V; Io_A: 0.002; Value1: W; U/M: EA
D8 = SML-LX0603GW-TR: LED, Green, SMD; Manufacturer: Lumex; Vf_V: 2.2; Value2: 2.2V; Io_A: 0.02; Tjmax_C: 85; Value1: W; U/M: EA
D9 = 150060YS75000: LED, Yellow, SMD; Manufacturer: Wurth Elektronik eiSos; Type: AlInGaP; Vf_V: 2; Value2: 2V; Io_A: 0.02; Value1: W; U/M: EA
J15-J21 = 61300211121: Header, 2.54 mm, 2x1, Gold, TH; Manufacturer: Wurth Elektronik; SymbolCreator: a0412235; U/M: EA
J22 J23 = 61300311121: Header, 2.54 mm, 3x1, Gold, TH; Manufacturer: Wurth Elektronik; SymbolCreator: a0799628; U/M: EA
J24 = 61300211121: as J14 on sheet WCS002A_HostInterface_ADC
L8 = BRC2012T2R2MD: Inductor, Wirewound, 2.2 µH, 1 A, 0.143 ohm, SMD; Manufacturer: Taiyo Yuden; Value: 2.2uH; Ind_H: 2.2E-6; Imax_A: 1; Irms: 1A @ 40C rise; Isat: 1.1A @ 30% inductance drop; DCR_ohm: 0.143; Value2: 1A; AEC Category: Q200
Q2 = BSS84DW-7-F: MOSFET, P-CH, -50 V, -0.13 A, AEC-Q101, SOT-363; Manufacturer: Diodes Inc.; Alternate Manufacturer: None; SymbolCreator: Altium; U/M: EA; ChType: P; Value: -50V; Value1: ? ohm; Value2: ? nC; Vgs_V: 20; AEC Category: Q101; AEC Qualified: Y
Q3 Q5 = FDN358P: MOSFET, P-CH, -30 V, -1.5 A, SSOT-3; Manufacturer: Fairchild Semiconductor; Alternate Manufacturer: None; U/M: EA; ChType: P; Value: -30V; Value1: 0.2 ohm; Rdson45_ohm: 0.2; Value2: 4 nC; QgTyp_nC: 4; Vgs_V: 20
Q4 Q6 Q7 = BSS138: MOSFET, N-CH, 50 V, 0.22 A, SOT-23; Manufacturer: Fairchild Semiconductor; Alternate Manufacturer: None; U/M: EA; ChType: N; Value: 50V; VdsMax_V: 50; Value1: 6 ohm; Rdson45_ohm: 6; Value2: 1.7 nC; QgTyp_nC: 1.7; Vgs_V: 20; IdsMax_A: 0.22
R116 R117 R120-R124 R126-R135 R154 = ERJ-2GE0R00X: as R54 on sheet WCS002A_HostInterface_ADC
R118 R119 = CRCW04023K30JNED: RES, 3.3 k, 5%, 0.063 W, 0402; Manufacturer: Vishay-Dale; CompType: Resistor; Value: 3.3k; Res_ohm: 3300; Value_Code: 3k30; Tolerance_%: 5; Power_W: 0.063; Value2: 0.063W; VDC_V: 50; TempCo: 200 ppm/C; EIA_Code: E24; U/M: EA
R125 = ERJ-6GEY0R00V: RES, 0, 5%, 0.125 W, 0805; Manufacturer: Panasonic; CompType: Resistor; Value: 0; Value_Code: 0000; Tolerance_%: 5; Power_W: 0.125; Value2: 0.125W; VDC_V: 150; TempCo: 600 ppm/C; EIA_Code: E24; U/M: EA; AEC Category: Q200
R136 R146 R151-R153 = CRCW0402100KJNED: RES, 100 k, 5%, 0.063 W, 0402; Manufacturer: Vishay-Dale; CompType: Resistor; Value: 100k; Res_ohm: 100000; Tolerance_%: 5; Power_W: 0.063; Value2: 0.063W; VDC_V: 50; TempCo: 200 ppm/C; EIA_Code: E24; U/M: EA
R137-R139 R144 = CRCW04021K00JNED: RES, 1.0 k, 5%, 0.063 W, 0402; Manufacturer: Vishay-Dale; CompType: Resistor; Value: 1.0k; Res_ohm: 1000; Value_Code: 1k00; Tolerance_%: 5; Power_W: 0.063; Value2: 0.063W; VDC_V: 50; TempCo: 200 ppm/C; EIA_Code: E24; U/M: EA
R140 = ERJ-2RKF1003X: RES, 100 k, 1%, 0.1 W, 0402; Manufacturer: Panasonic; CompType: Resistor; Value: 100k; Res_ohm: 100000; Tolerance_%: 1; Power_W: 0.1; Value2: 0.1W; VDC_V: 50; TempCo: 100 ppm/C; EIA_Code: E96; U/M: EA; AEC Category: Q200
R141 R142 = CRCW040210K0JNED: RES, 10 k, 5%, 0.063 W, 0402; Manufacturer: Vishay-Dale; CompType: Resistor; Value: 10k; Res_ohm: 10000; Value_Code: 10k0; Tolerance_%: 5; Power_W: 0.063; Value2: 0.063W; VDC_V: 50; TempCo: 200 ppm/C; EIA_Code: E24; U/M: EA
R143 R145 R147-R149 = CRCW0603270RJNEA: RES, 270, 5%, 0.1 W, 0603; Manufacturer: Vishay-Dale; CompType: Resistor; Value: 270; Value_Code: 270R; Tolerance_%: 5; Power_W: 0.1; Value2: 0.1W; VDC_V: 75; TempCo: 200 ppm/C; EIA_Code: E24; U/M: EA
R150 = ERJ-3GEY0R00V: as R56 on sheet WCS002A_HostInterface_ADC
SW2 SW3 = MJTP1117: Switch, SPST-NO, Off-Mom, 1 Pos, 0.05A, 12VDC, TH; Manufacturer: APEM; SymbolCreator: a0799628; VDC_V: 12; PositionCount: 1; CurrentRating_mA: 50
SW4 = EVQ-PSD02K: Switch, Tactile, SPST-NO, SMT; Manufacturer: Panasonic; SymbolCreator: a0799628; VDC_V: 12; SwitchFunction: Off-Mom; PositionCount: 1; CurrentRating_mA: 50
TP2 = 5015: Test Point, Miniature, SMT; Manufacturer: Keystone; CompType: Test Point Loop; U/M: EA
U10 = TMP006AIYZF: Infrared Thermopile Sensor in Chip-Scale Package, YZF0008AEAE; Manufacturer: Texas Instruments; SymbolCreator: a0411947; CompType: IC; U/M: EA
U11 = BMA222E: Digital, triaxial acceleration sensor, 12LGA; Manufacturer: Bosch Solar Energy; SymbolCreator: Altium
U12 = TPS62162DSGR: Buck Step Down Regulator with 3 to 17 V Input and 3.3 V Output, -40 to 85 degC, 8-Pin WSON (DSG), Green (RoHS & no Sb/Br); Manufacturer: Texas Instruments; Alternate PartNumber: Equivalent; Duty Cycle(Max)(%): 100; Iout(Max)(A): 1; Iq(Typ)(mA): 0.017; Preset Vout(V): 3.3; Rating: Catalog; SubFamily: Step-Down Regulator; Switch Current Limit(Typ)(A): 1.8; Synchronous Rectification: TRUE; Vin(Max)(V): 17; Vin(Min)(V): 3

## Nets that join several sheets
GND: WCS002A_EmulationCircuit (64 pins), WCS002A_EngineArea (46 pins), WCS002A_HostInterface_ADC (12 pins), WCS002A_PowerLedsSwitchSensors (33 pins)
VBAT_CC: WCS002A_EmulationCircuit (J7.3 J7.4 R30.2), WCS002A_EngineArea (10 pins), WCS002A_HostInterface_ADC (R56.1), WCS002A_PowerLedsSwitchSensors (5 pins)
VBUS_USB1: WCS002A_EmulationCircuit (L1.2 R13.1 R15.1), WCS002A_PowerLedsSwitchSensors (C62.1 J20.2 U12.2 U12.3)
VCC_5V: WCS002A_HostInterface_ADC (P3.1), WCS002A_PowerLedsSwitchSensors (J20.1 J23.1)
VCC_BRD: WCS002A_EmulationCircuit (R32.1), WCS002A_EngineArea (R38.2 R47.1), WCS002A_HostInterface_ADC (J14.1 R57.1), WCS002A_PowerLedsSwitchSensors (17 pins)
VCC_LDO_3V3: WCS002A_EmulationCircuit (37 pins), WCS002A_PowerLedsSwitchSensors (8 pins)
VCC_SENSE: WCS002A_EmulationCircuit (10 pins), WCS002A_PowerLedsSwitchSensors (J18.1)
CC_nRESET: WCS002A_EmulationCircuit (J3.10 J8.10), WCS002A_EngineArea (C27.1 J12.2 R35.2 U7.32), WCS002A_PowerLedsSwitchSensors (D5.1)
LP_GPIO_01: WCS002A_EmulationCircuit (J5.1), WCS002A_HostInterface_ADC (R82.2)
LP_GPIO_02: WCS002A_EmulationCircuit (J6.1), WCS002A_HostInterface_ADC (C54.1 R101.2 R105.2)
LP_RESET_OUT: WCS002A_HostInterface_ADC (P2.5), WCS002A_PowerLedsSwitchSensors (D5.2 R136.2)
P01_GPIO_10: WCS002A_EmulationCircuit (J7.9), WCS002A_EngineArea (U7.1), WCS002A_HostInterface_ADC (R59.1 R89.1), WCS002A_PowerLedsSwitchSensors (Q6.1 R123.1 R152.1)
P02_GPIO_11: WCS002A_EmulationCircuit (J7.11), WCS002A_EngineArea (U7.2), WCS002A_HostInterface_ADC (R58.1 R91.1), WCS002A_PowerLedsSwitchSensors (Q4.1 R129.1 R151.1)
P03_GPIO_12: WCS002A_EngineArea (U7.3), WCS002A_HostInterface_ADC (R71.1)
P04_GPIO_13: WCS002A_EngineArea (U7.4), WCS002A_HostInterface_ADC (R67.1), WCS002A_PowerLedsSwitchSensors (R125.2 R141.1 SW2.1)
P05_GPIO_14: WCS002A_EngineArea (U7.5), WCS002A_HostInterface_ADC (R83.1)
P06_GPIO_15: WCS002A_EngineArea (U7.6), WCS002A_HostInterface_ADC (R74.2 R97.2)
P07_GPIO_16: WCS002A_EngineArea (U7.7), WCS002A_HostInterface_ADC (R70.2 R99.2)
P08_GPIO_17: WCS002A_EngineArea (U7.8), WCS002A_HostInterface_ADC (R62.2)
P15_GPIO_22: WCS002A_EngineArea (U7.15), WCS002A_HostInterface_ADC (R86.2), WCS002A_PowerLedsSwitchSensors (R142.1 SW3.1)
P16_GPIO_23: WCS002A_EngineArea (R45.2), WCS002A_HostInterface_ADC (R81.1 R95.1), WCS002A_PowerLedsSwitchSensors (R124.1)
P16_JTAG_TDI: WCS002A_EmulationCircuit (J3.4 J8.8), WCS002A_EngineArea (R45.1 U7.16)
P17_GPIO_24: WCS002A_EngineArea (R46.2), WCS002A_HostInterface_ADC (R61.1 R85.1 R96.1), WCS002A_PowerLedsSwitchSensors (R131.1)
P17_JTAG_TDO: WCS002A_EmulationCircuit (J3.2 J8.6), WCS002A_EngineArea (R46.1 U7.17)
P18_GPIO_28: WCS002A_EngineArea (U7.18), WCS002A_HostInterface_ADC (R60.2 R69.1)
P19_JTAG_TCK: WCS002A_EmulationCircuit (J3.6 J8.4), WCS002A_EngineArea (R48.1 U7.19)
P20_JTAG_TMS: WCS002A_EmulationCircuit (J3.8 J8.2), WCS002A_EngineArea (U7.20)
P21_GPIO_25: WCS002A_EngineArea (R52.2), WCS002A_HostInterface_ADC (R66.1 R78.2)
P29_GPIO_26: WCS002A_EngineArea (U7.29), WCS002A_HostInterface_ADC (R54.1)
P30_GPIO_27: WCS002A_EngineArea (U7.30), WCS002A_HostInterface_ADC (R55.1)
P45_GPIO_31: WCS002A_EngineArea (R42.2), WCS002A_HostInterface_ADC (R64.2)
P50_GPIO_00: WCS002A_EngineArea (U7.50), WCS002A_HostInterface_ADC (R92.2 R93.1)
P53_GPIO_30: WCS002A_EngineArea (U7.53), WCS002A_HostInterface_ADC (R88.2)
P55_GPIO_01: WCS002A_EmulationCircuit (J5.2 R34.1), WCS002A_EngineArea (U7.55)
P57_GPIO_02: WCS002A_EmulationCircuit (J6.2 R33.1), WCS002A_EngineArea (U7.57)
P58_GPIO_03: WCS002A_EngineArea (U7.58), WCS002A_HostInterface_ADC (C55.1 R108.2 R110.2)
P59_GPIO_04: WCS002A_EngineArea (U7.59), WCS002A_HostInterface_ADC (C56.1 R109.2 R111.2)
P60_GPIO_05: WCS002A_EngineArea (U7.60), WCS002A_HostInterface_ADC (C53.1 R77.1 R100.2 R102.2)
P61_GPIO_06: WCS002A_EngineArea (U7.61), WCS002A_HostInterface_ADC (R75.1 R98.1)
P62_GPIO_07: WCS002A_EngineArea (U7.62), WCS002A_HostInterface_ADC (R73.1 R87.1 R94.1)
P63_GPIO_08: WCS002A_EngineArea (U7.63), WCS002A_HostInterface_ADC (R84.2)
P64_GPIO_09: WCS002A_EngineArea (U7.64), WCS002A_HostInterface_ADC (R63.1 R90.2), WCS002A_PowerLedsSwitchSensors (Q7.1 R153.1)
SOP0: WCS002A_EngineArea (J13.2 R49.1 U7.35), WCS002A_PowerLedsSwitchSensors (Q2.3)
SOP1: WCS002A_EngineArea (J13.4 R50.1 U7.34), WCS002A_PowerLedsSwitchSensors (Q2.6)

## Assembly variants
001: not fitted FID1 FID2 FID3 FID4 FID5 FID6 J2 J12 R37 R38 R42 R43 R54 R55 R57 R58 R59 R61 R63 R65 R66 R69 R73 R77 R79 R93 R94 R95 R96 R97 R98 R99 R100 R101 R108 R109 R120 R122 R124 R125 R127 R131 R150
002: not fitted FID1 FID2 FID3 FID4 FID5 FID6 J2 J12 J14 L7 R37 R38 R42 R54 R55 R56 R58 R59 R61 R63 R65 R66 R69 R73 R77 R79 R93 R94 R95 R96 R97 R98 R99 R100 R101 R108 R109 R120 R122 R124 R125 R127 R131 R150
